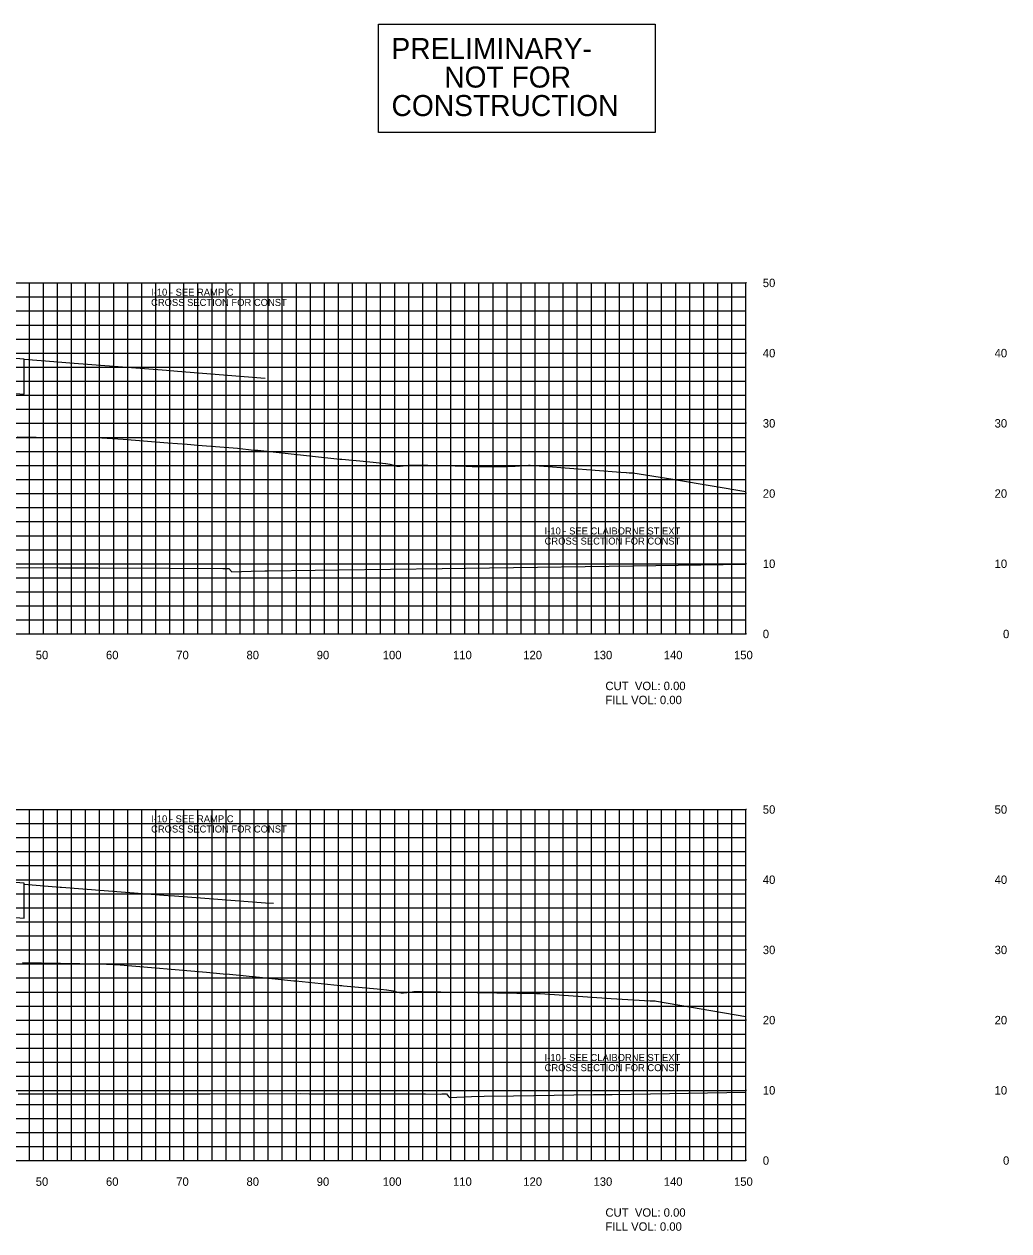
# Model space of a CAD drawing. Extents: x 1800880 to 1814006, y 250083 to 250560.
# Drawn here: x 1811518.3 to 1811658.4, y 250089.4 to 250261.3 of the extents above; entities that cross this region are included whole.
import ezdxf

# ---------------------------------------------------------------- set-up
doc = ezdxf.new("R2010")
doc.units = 0
for name, color, linetype in [('33', 7, 'Continuous'), ('CL-CNST', 7, 'Continuous'), ('DESIGN - DRAINAGE - Bridges', 7, 'Continuous'), ('DRAINAGETXT', 7, 'Continuous'), ('EPTEXT', 7, 'Continuous'), ('Level 32', 7, 'Continuous'), ('Level 46', 7, 'Continuous'), ('Level 62', 7, 'Continuous'), ('TOPO', 7, 'Continuous')]:
    doc.layers.add(name, color=color, linetype=linetype)

msp = doc.modelspace()

# ---------------------------------------------------------------- linework, layer by layer
at = {"layer": 'CL-CNST'}
for points in [[(1811517.27, 250202.51), (1811522.72, 250202.43), (1811529.29, 250202.35), (1811532.33, 250202.18), (1811532.34, 250202.18), (1811532.34, 250202.18), (1811538.71, 250201.67), (1811541.45, 250201.45), (1811542.98, 250201.33), (1811548.61, 250200.87), (1811550.96, 250200.6), (1811551.38, 250200.59), (1811551.53, 250200.59), (1811563.21, 250199.31), (1811563.49, 250199.31), (1811567.05, 250198.99), (1811569.69, 250198.73), (1811569.74, 250198.73), (1811570.32, 250198.6), (1811571.14, 250198.36), (1811571.22, 250198.36), (1811571.32, 250198.34), (1811571.78, 250198.34), (1811573.07, 250198.45), (1811573.26, 250198.49), (1811573.4, 250198.49), (1811573.41, 250198.49), (1811573.42, 250198.49), (1811573.43, 250198.49), (1811573.44, 250198.49), (1811573.46, 250198.49), (1811573.47, 250198.49), (1811573.49, 250198.49), (1811573.5, 250198.49), (1811573.52, 250198.49), (1811573.54, 250198.49), (1811573.57, 250198.49), (1811573.59, 250198.49), (1811573.62, 250198.49), (1811573.66, 250198.49), (1811573.7, 250198.49), (1811573.75, 250198.49), (1811573.82, 250198.49), (1811573.9, 250198.49), (1811574, 250198.49), (1811574.13, 250198.49), (1811574.32, 250198.49), (1811574.6, 250198.49), (1811574.65, 250198.49), (1811575.72, 250198.46), (1811579.59, 250198.36), (1811581.17, 250198.32), (1811582.03, 250198.3), (1811587.03, 250198.28), (1811587.88, 250198.33), (1811588.15, 250198.33), (1811590.07, 250198.45), (1811590.28, 250198.46), (1811592.25, 250198.31), (1811603.21, 250197.49), (1811603.94, 250197.44), (1811603.98, 250197.43), (1811604.39, 250197.4), (1811604.89, 250197.4), (1811604.91, 250197.4), (1811610.6, 250196.47), (1811611.11, 250196.38), (1811621, 250194.71)], [(1811518.04, 250127.63), (1811528.9, 250127.47), (1811531.01, 250127.35), (1811531.94, 250127.3), (1811544.23, 250126.24), (1811546.6, 250126.04), (1811547.5, 250125.96), (1811547.98, 250125.92), (1811549.45, 250125.8), (1811550.71, 250125.65), (1811550.84, 250125.64), (1811556.64, 250125.05), (1811556.95, 250125.05), (1811563.24, 250124.36), (1811563.49, 250124.35), (1811563.73, 250124.33), (1811569.01, 250123.85), (1811569.82, 250123.76), (1811569.9, 250123.76), (1811570.78, 250123.58), (1811571.4, 250123.4), (1811571.45, 250123.4), (1811571.9, 250123.32), (1811572.24, 250123.32), (1811573.22, 250123.4), (1811573.72, 250123.49), (1811574.11, 250123.49), (1811574.14, 250123.49), (1811574.16, 250123.49), (1811574.19, 250123.49), (1811574.22, 250123.49), (1811574.26, 250123.49), (1811574.29, 250123.49), (1811574.33, 250123.49), (1811574.38, 250123.49), (1811574.43, 250123.49), (1811574.48, 250123.49), (1811574.55, 250123.49), (1811574.62, 250123.49), (1811574.71, 250123.49), (1811574.81, 250123.49), (1811574.92, 250123.49), (1811574.99, 250123.49), (1811582.74, 250123.37), (1811591.19, 250123.23), (1811591.73, 250123.2), (1811601.8, 250122.53), (1811607.38, 250122.18), (1811607.47, 250122.17), (1811607.5, 250122.17), (1811607.5, 250122.17), (1811607.51, 250122.17), (1811608.06, 250122.16), (1811608.07, 250122.16), (1811608.26, 250122.13), (1811621, 250119.95)]]:
    msp.add_lwpolyline(points, dxfattribs=at)
at = {"layer": 'DESIGN - DRAINAGE - Bridges'}
for p, q in [((1811621, 250174.43), (1811621, 250224.43)), ((1811621.06, 250224.43), (1811621, 250224.43)), ((1811621.06, 250214.43), (1811621, 250214.43)), ((1811621.06, 250204.43), (1811621, 250204.43)), ((1811621.06, 250194.43), (1811621, 250194.43)), ((1811621.06, 250184.43), (1811621, 250184.43)), ((1811321, 250174.43), (1811621, 250174.43)), ((1811521, 250174.37), (1811521, 250174.43)), ((1811531, 250174.37), (1811531, 250174.43)), ((1811541, 250174.37), (1811541, 250174.43)), ((1811551, 250174.37), (1811551, 250174.43)), ((1811561, 250174.37), (1811561, 250174.43)), ((1811571, 250174.37), (1811571, 250174.43)), ((1811581, 250174.37), (1811581, 250174.43)), ((1811591, 250174.37), (1811591, 250174.43)), ((1811601, 250174.37), (1811601, 250174.43)), ((1811611, 250174.37), (1811611, 250174.43)), ((1811621, 250174.37), (1811621, 250174.43)), ((1811621.06, 250174.43), (1811621, 250174.43)), ((1811621, 250099.43), (1811621, 250149.43)), ((1811621.06, 250149.43), (1811621, 250149.43)), ((1811621.06, 250139.43), (1811621, 250139.43)), ((1811621.06, 250129.43), (1811621, 250129.43)), ((1811621.06, 250119.43), (1811621, 250119.43)), ((1811621.06, 250109.43), (1811621, 250109.43)), ((1811321, 250099.43), (1811621, 250099.43)), ((1811521, 250099.37), (1811521, 250099.43)), ((1811531, 250099.37), (1811531, 250099.43)), ((1811541, 250099.37), (1811541, 250099.43)), ((1811551, 250099.37), (1811551, 250099.43)), ((1811561, 250099.37), (1811561, 250099.43)), ((1811571, 250099.37), (1811571, 250099.43)), ((1811581, 250099.37), (1811581, 250099.43)), ((1811591, 250099.37), (1811591, 250099.43)), ((1811601, 250099.37), (1811601, 250099.43)), ((1811611, 250099.37), (1811611, 250099.43)), ((1811621, 250099.37), (1811621, 250099.43)), ((1811621.06, 250099.43), (1811621, 250099.43))]:
    msp.add_line(p, q, dxfattribs=at)
at = {"layer": 'Level 32'}
msp.add_lwpolyline([(1811568.68, 250261.29), (1811608.08, 250261.29), (1811608.08, 250245.85), (1811568.68, 250245.85)], close=True, dxfattribs=at)
at = {"layer": 'Level 46'}
for p, q in [((1811321, 250224.43), (1811621, 250224.43)), ((1811519, 250174.43), (1811519, 250224.43)), ((1811521, 250174.43), (1811521, 250224.43)), ((1811523, 250174.43), (1811523, 250224.43)), ((1811525, 250174.43), (1811525, 250224.43)), ((1811527, 250174.43), (1811527, 250224.43)), ((1811529, 250174.43), (1811529, 250224.43)), ((1811531, 250174.43), (1811531, 250224.43)), ((1811533, 250174.43), (1811533, 250224.43)), ((1811535, 250174.43), (1811535, 250224.43)), ((1811537, 250174.43), (1811537, 250224.43)), ((1811539, 250174.43), (1811539, 250224.43)), ((1811541, 250174.43), (1811541, 250224.43)), ((1811543, 250174.43), (1811543, 250224.43)), ((1811545, 250174.43), (1811545, 250224.43)), ((1811547, 250174.43), (1811547, 250224.43)), ((1811549, 250174.43), (1811549, 250224.43)), ((1811551, 250174.43), (1811551, 250224.43)), ((1811553, 250174.43), (1811553, 250224.43)), ((1811555, 250174.43), (1811555, 250224.43)), ((1811557, 250174.43), (1811557, 250224.43)), ((1811559, 250174.43), (1811559, 250224.43)), ((1811561, 250174.43), (1811561, 250224.43)), ((1811563, 250174.43), (1811563, 250224.43)), ((1811565, 250174.43), (1811565, 250224.43)), ((1811567, 250174.43), (1811567, 250224.43)), ((1811569, 250174.43), (1811569, 250224.43)), ((1811571, 250174.43), (1811571, 250224.43)), ((1811573, 250174.43), (1811573, 250224.43)), ((1811575, 250174.43), (1811575, 250224.43)), ((1811577, 250174.43), (1811577, 250224.43)), ((1811579, 250174.43), (1811579, 250224.43)), ((1811581, 250174.43), (1811581, 250224.43)), ((1811583, 250174.43), (1811583, 250224.43)), ((1811585, 250174.43), (1811585, 250224.43)), ((1811587, 250174.43), (1811587, 250224.43)), ((1811589, 250174.43), (1811589, 250224.43)), ((1811591, 250174.43), (1811591, 250224.43)), ((1811593, 250174.43), (1811593, 250224.43)), ((1811595, 250174.43), (1811595, 250224.43)), ((1811597, 250174.43), (1811597, 250224.43)), ((1811599, 250174.43), (1811599, 250224.43)), ((1811601, 250174.43), (1811601, 250224.43)), ((1811603, 250174.43), (1811603, 250224.43)), ((1811605, 250174.43), (1811605, 250224.43)), ((1811607, 250174.43), (1811607, 250224.43)), ((1811609, 250174.43), (1811609, 250224.43)), ((1811611, 250174.43), (1811611, 250224.43)), ((1811613, 250174.43), (1811613, 250224.43)), ((1811615, 250174.43), (1811615, 250224.43)), ((1811617, 250174.43), (1811617, 250224.43)), ((1811619, 250174.43), (1811619, 250224.43)), ((1811621, 250174.43), (1811621, 250224.43)), ((1811321, 250222.43), (1811621, 250222.43)), ((1811321, 250220.43), (1811621, 250220.43)), ((1811321, 250218.43), (1811621, 250218.43)), ((1811321, 250216.43), (1811621, 250216.43)), ((1811321, 250214.43), (1811621, 250214.43)), ((1811321, 250212.43), (1811621, 250212.43)), ((1811321, 250210.43), (1811621, 250210.43)), ((1811321, 250208.43), (1811621, 250208.43)), ((1811321, 250206.43), (1811621, 250206.43)), ((1811321, 250204.43), (1811621, 250204.43)), ((1811321, 250202.43), (1811621, 250202.43)), ((1811321, 250200.43), (1811621, 250200.43)), ((1811321, 250198.43), (1811621, 250198.43)), ((1811321, 250196.43), (1811621, 250196.43)), ((1811321, 250194.43), (1811621, 250194.43)), ((1811321, 250192.43), (1811621, 250192.43)), ((1811321, 250190.43), (1811621, 250190.43)), ((1811321, 250188.43), (1811621, 250188.43)), ((1811321, 250186.43), (1811621, 250186.43)), ((1811321, 250184.43), (1811621, 250184.43)), ((1811321, 250182.43), (1811621, 250182.43)), ((1811321, 250180.43), (1811621, 250180.43)), ((1811321, 250178.43), (1811621, 250178.43)), ((1811321, 250176.43), (1811621, 250176.43)), ((1811321, 250174.43), (1811621, 250174.43)), ((1811321, 250149.43), (1811621, 250149.43)), ((1811519, 250099.43), (1811519, 250149.43)), ((1811521, 250099.43), (1811521, 250149.43)), ((1811523, 250099.43), (1811523, 250149.43)), ((1811525, 250099.43), (1811525, 250149.43)), ((1811527, 250099.43), (1811527, 250149.43)), ((1811529, 250099.43), (1811529, 250149.43)), ((1811531, 250099.43), (1811531, 250149.43)), ((1811533, 250099.43), (1811533, 250149.43)), ((1811535, 250099.43), (1811535, 250149.43)), ((1811537, 250099.43), (1811537, 250149.43)), ((1811539, 250099.43), (1811539, 250149.43)), ((1811541, 250099.43), (1811541, 250149.43)), ((1811543, 250099.43), (1811543, 250149.43)), ((1811545, 250099.43), (1811545, 250149.43)), ((1811547, 250099.43), (1811547, 250149.43)), ((1811549, 250099.43), (1811549, 250149.43)), ((1811551, 250099.43), (1811551, 250149.43)), ((1811553, 250099.43), (1811553, 250149.43)), ((1811555, 250099.43), (1811555, 250149.43)), ((1811557, 250099.43), (1811557, 250149.43)), ((1811559, 250099.43), (1811559, 250149.43)), ((1811561, 250099.43), (1811561, 250149.43)), ((1811563, 250099.43), (1811563, 250149.43)), ((1811565, 250099.43), (1811565, 250149.43)), ((1811567, 250099.43), (1811567, 250149.43)), ((1811569, 250099.43), (1811569, 250149.43)), ((1811571, 250099.43), (1811571, 250149.43)), ((1811573, 250099.43), (1811573, 250149.43)), ((1811575, 250099.43), (1811575, 250149.43)), ((1811577, 250099.43), (1811577, 250149.43)), ((1811579, 250099.43), (1811579, 250149.43)), ((1811581, 250099.43), (1811581, 250149.43)), ((1811583, 250099.43), (1811583, 250149.43)), ((1811585, 250099.43), (1811585, 250149.43)), ((1811587, 250099.43), (1811587, 250149.43)), ((1811589, 250099.43), (1811589, 250149.43)), ((1811591, 250099.43), (1811591, 250149.43)), ((1811593, 250099.43), (1811593, 250149.43)), ((1811595, 250099.43), (1811595, 250149.43)), ((1811597, 250099.43), (1811597, 250149.43)), ((1811599, 250099.43), (1811599, 250149.43)), ((1811601, 250099.43), (1811601, 250149.43)), ((1811603, 250099.43), (1811603, 250149.43)), ((1811605, 250099.43), (1811605, 250149.43)), ((1811607, 250099.43), (1811607, 250149.43)), ((1811609, 250099.43), (1811609, 250149.43)), ((1811611, 250099.43), (1811611, 250149.43)), ((1811613, 250099.43), (1811613, 250149.43)), ((1811615, 250099.43), (1811615, 250149.43)), ((1811617, 250099.43), (1811617, 250149.43)), ((1811619, 250099.43), (1811619, 250149.43)), ((1811621, 250099.43), (1811621, 250149.43)), ((1811321, 250147.43), (1811621, 250147.43)), ((1811321, 250145.43), (1811621, 250145.43)), ((1811321, 250143.43), (1811621, 250143.43)), ((1811321, 250141.43), (1811621, 250141.43)), ((1811321, 250139.43), (1811621, 250139.43)), ((1811321, 250137.43), (1811621, 250137.43)), ((1811321, 250135.43), (1811621, 250135.43)), ((1811321, 250133.43), (1811621, 250133.43)), ((1811321, 250131.43), (1811621, 250131.43)), ((1811321, 250129.43), (1811621, 250129.43)), ((1811321, 250127.43), (1811621, 250127.43)), ((1811321, 250125.43), (1811621, 250125.43)), ((1811321, 250123.43), (1811621, 250123.43)), ((1811321, 250121.43), (1811621, 250121.43)), ((1811321, 250119.43), (1811621, 250119.43)), ((1811321, 250117.43), (1811621, 250117.43)), ((1811321, 250115.43), (1811621, 250115.43)), ((1811321, 250113.43), (1811621, 250113.43)), ((1811321, 250111.43), (1811621, 250111.43)), ((1811321, 250109.43), (1811621, 250109.43)), ((1811321, 250107.43), (1811621, 250107.43)), ((1811321, 250105.43), (1811621, 250105.43)), ((1811321, 250103.43), (1811621, 250103.43)), ((1811321, 250101.43), (1811621, 250101.43)), ((1811321, 250099.43), (1811621, 250099.43))]:
    msp.add_line(p, q, dxfattribs=at)
at = {"layer": 'Level 62'}
for points in [[(1811518.25, 250213.57), (1811522.5, 250213.24), (1811524.76, 250213.06), (1811538.53, 250211.98), (1811540.1, 250211.85), (1811552.56, 250210.87)], [(1811496.19, 250183.9), (1811523.31, 250183.86), (1811523.37, 250183.86), (1811526.18, 250183.86), (1811528.27, 250183.83), (1811528.72, 250183.83), (1811538.88, 250183.79), (1811546.53, 250183.76), (1811546.54, 250183.76), (1811546.54, 250183.76), (1811546.66, 250183.76), (1811547.38, 250183.77), (1811547.76, 250183.32), (1811547.81, 250183.27), (1811550.56, 250183.36), (1811552.53, 250183.43), (1811552.89, 250183.44), (1811559.66, 250183.53), (1811563.07, 250183.57), (1811577.75, 250183.75), (1811584.48, 250183.84), (1811604.94, 250184.13), (1811621, 250184.38)], [(1811518.25, 250138.79), (1811523.4, 250138.39), (1811523.59, 250138.37), (1811538.74, 250137.2), (1811539.67, 250137.14), (1811552.59, 250136.14), (1811553.75, 250136.07)], [(1811517.38, 250108.94), (1811544.4, 250108.95), (1811544.69, 250108.94), (1811557.63, 250108.97), (1811558.83, 250108.95), (1811560.12, 250108.94), (1811571.99, 250108.91), (1811575.37, 250108.91), (1811577.53, 250108.9), (1811577.54, 250108.9), (1811577.54, 250108.9), (1811577.71, 250108.91), (1811578.36, 250108.91), (1811578.68, 250108.53), (1811578.78, 250108.41), (1811581.94, 250108.53), (1811583.75, 250108.6), (1811587.9, 250108.66), (1811593.71, 250108.74), (1811599.29, 250108.82), (1811601.95, 250108.86), (1811621, 250109.15)]]:
    msp.add_lwpolyline(points, dxfattribs=at)
at = {"layer": 'TOPO'}
for points in [[(1811506.25, 250209.55), (1811518.25, 250208.59), (1811518.25, 250213.55), (1811506.25, 250214.51), (1811494.25, 250215.47), (1811482.25, 250216.43), (1811472.25, 250217.23), (1811471, 250217.33), (1811471, 250212.37), (1811472.25, 250212.27), (1811482.25, 250211.47), (1811494.25, 250210.51)], [(1811506.25, 250134.89), (1811518.25, 250133.97), (1811518.25, 250138.93), (1811506.25, 250139.85), (1811494.25, 250140.76), (1811482.25, 250141.68), (1811472.25, 250142.45), (1811471, 250142.55), (1811471, 250137.59), (1811472.25, 250137.49), (1811482.25, 250136.72), (1811494.25, 250135.8)]]:
    msp.add_lwpolyline(points, close=True, dxfattribs=at)

# ---------------------------------------------------------------- texts
for s, p in [('50', (1811519.9, 250170.83)), ('60', (1811529.9, 250170.83)), ('70', (1811539.9, 250170.83)), ('80', (1811549.9, 250170.83)), ('90', (1811559.9, 250170.83)), ('100', (1811569.3, 250170.83)), ('110', (1811579.3, 250170.83)), ('120', (1811589.3, 250170.83)), ('130', (1811599.3, 250170.83)), ('140', (1811609.3, 250170.83)), ('150', (1811619.3, 250170.83)), ('50', (1811519.9, 250095.83)), ('60', (1811529.9, 250095.83)), ('70', (1811539.9, 250095.83)), ('80', (1811549.9, 250095.83)), ('90', (1811559.9, 250095.83)), ('100', (1811569.3, 250095.83)), ('110', (1811579.3, 250095.83)), ('120', (1811589.3, 250095.83)), ('130', (1811599.3, 250095.83)), ('140', (1811609.3, 250095.83)), ('150', (1811619.3, 250095.83))]:
    msp.add_text(s, height=1.2).set_placement(p)
at = {"layer": '33'}
for s, p in [('50', (1811623.4, 250223.83)), ('40', (1811623.4, 250213.83)), ('40', (1811656.4, 250213.83)), ('30', (1811623.4, 250203.83)), ('30', (1811656.4, 250203.83)), ('20', (1811623.4, 250193.83)), ('20', (1811656.4, 250193.83)), ('10', (1811623.4, 250183.83)), ('10', (1811656.4, 250183.83)), ('0', (1811623.4, 250173.83)), ('0', (1811657.6, 250173.83)), ('50', (1811623.4, 250148.83)), ('50', (1811656.4, 250148.83)), ('40', (1811623.4, 250138.83)), ('40', (1811656.4, 250138.83)), ('30', (1811623.4, 250128.83)), ('30', (1811656.4, 250128.83)), ('20', (1811623.4, 250118.83)), ('20', (1811656.4, 250118.83)), ('10', (1811623.4, 250108.83)), ('10', (1811656.4, 250108.83)), ('0', (1811623.4, 250098.83)), ('0', (1811657.6, 250098.83))]:
    msp.add_text(s, height=1.2, dxfattribs=at).set_placement(p)
at = {"layer": 'DRAINAGETXT'}
for s, p in [('CUT  VOL: 0.00', (1811601, 250166.43)), ('FILL VOL: 0.00', (1811601, 250164.43)), ('CUT  VOL: 0.00', (1811601, 250091.43)), ('FILL VOL: 0.00', (1811601, 250089.43))]:
    msp.add_text(s, height=1.2, dxfattribs=at).set_placement(p)
at = {"layer": 'EPTEXT'}
for s, p in [('CROSS SECTION FOR CONST ', (1811536.32, 250221.15)), ('I-10 - SEE RAMP C', (1811536.32, 250222.6)), ('I-10 - SEE CLAIBORNE ST EXT', (1811592.34, 250188.6)), ('CROSS SECTION FOR CONST ', (1811592.34, 250187.16)), ('I-10 - SEE RAMP C', (1811536.32, 250147.6)), ('CROSS SECTION FOR CONST ', (1811536.32, 250146.15)), ('I-10 - SEE CLAIBORNE ST EXT', (1811592.34, 250113.6)), ('CROSS SECTION FOR CONST ', (1811592.34, 250112.16))]:
    msp.add_text(s, height=1, dxfattribs=at).set_placement(p)
at = {"layer": 'Level 32'}
for s, p in [('PRELIMINARY-', (1811570.54, 250256.31)), ('NOT FOR', (1811578.05, 250252.25)), ('CONSTRUCTION', (1811570.55, 250248.19))]:
    msp.add_text(s, height=3, dxfattribs=at).set_placement(p)

doc.saveas('drawing.dxf')
